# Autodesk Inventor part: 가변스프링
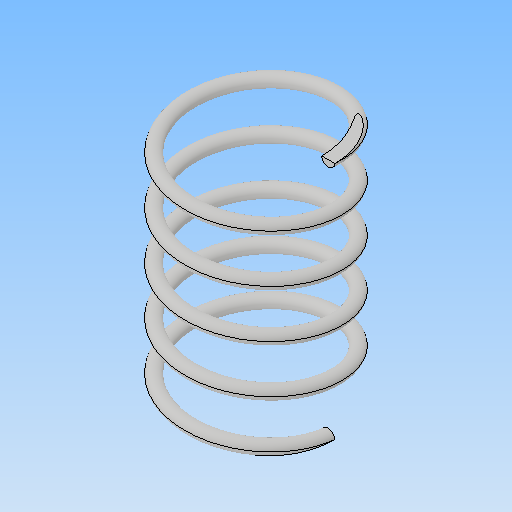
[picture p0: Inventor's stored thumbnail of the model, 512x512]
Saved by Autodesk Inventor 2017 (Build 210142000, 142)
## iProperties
Part Number: 가변스프링
Material: 일반
Document SubType Name: Modeling
Designer: MRC
Density: 1 g/cm^3
Appearance: 기본값
Mass: 1.07362 g
Surface Area: 21.7305 cm^2
Volume: 1.07362 cm^3
Author: MRC
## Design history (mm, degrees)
sketch "스케치1"
  geometry: L1 (0, 0)-(0, 36.411); L2 (0, 0)-(11, 0); L3 (0, 36.411)-(11, 36.411); C1 r 1 at (11, 0)
  constraints: 6 end point, 2 horizontal, 1 centre point, 1 coincident, 1 vertical
  dimensions: "d0" = 36.4112 distance of L1.start L1.end (derived); "d1" = 11 distance of L1.start L2.end; "d2" = 2 diameter of C1
feature "코일1" pitch "d3" = 10; turns "d5" = 5; dims "d4" = 36.4112 (= d0), "d6" = 0, angle "d7" = 90 deg, angle "d8" = 90 deg, "d9" = 0, "d10" = 0
sketch "스케치2"
  geometry: L1 (36.411, 15)-(0, 15); L2 (0, 15)-(0, -15); L3 (0, -15)-(36.411, -15); L4 (36.411, -15)-(36.411, 15); 2 further points
  constraints: 8 end point, 2 parallel, 1 coincident, 1 horizontal, 1 midpoint, 1 perpendicular
  dimensions: "d11" = 30 distance of L3.end L1.start; "d12" = 36.4112 distance of L2.end L3.end (= d0)
extrude "돌출1" sketch "스케치2" stored distance "d13" = 30; taper "d14" = 0 deg
node "솔리드1"
